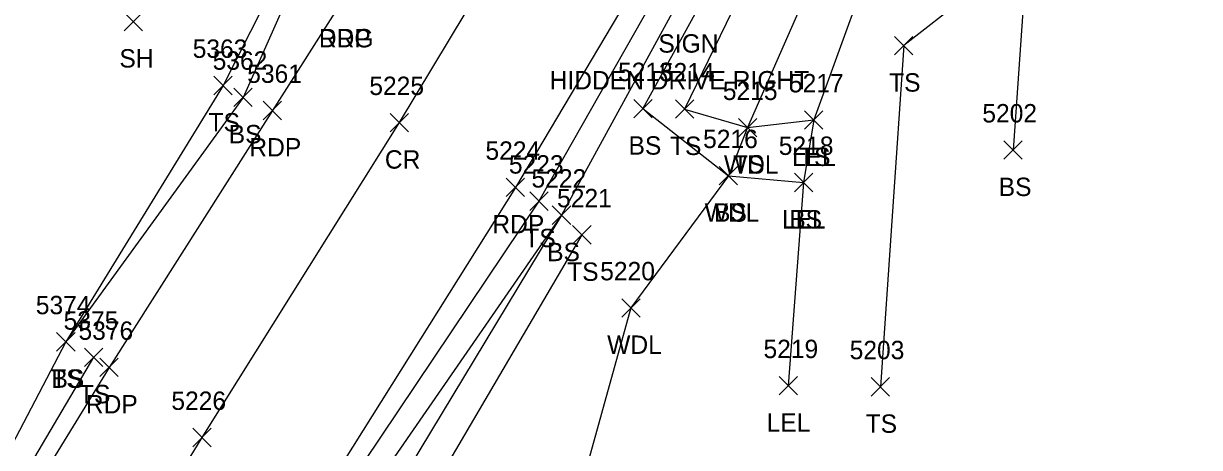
# Model space of a CAD drawing. Extents: x 1678863 to 1683592, y 407783 to 418211.
# Drawn here: x 1679773.8 to 1679901.7, y 411490.3 to 411536.4 of the extents above; entities that cross this region are included whole.
import ezdxf

# ---------------------------------------------------------------- set-up
doc = ezdxf.new("R2010")
doc.units = 0
for name, color, linetype in [('L_A', 7, 'Continuous'), ('L_I', 7, 'Continuous'), ('L_TIC', 7, 'Continuous'), ('LARO', 7, 'Continuous'), ('LAWA', 7, 'Continuous'), ('LELB', 7, 'Continuous'), ('P_A', 7, 'Continuous'), ('P_I', 7, 'Continuous'), ('P_TIC', 7, 'Continuous'), ('PET', 7, 'Continuous'), ('PRC', 7, 'Continuous'), ('R_A', 7, 'Continuous'), ('S_A', 7, 'Continuous'), ('S_C', 7, 'Continuous')]:
    doc.layers.add(name, color=color, linetype=linetype)

msp = doc.modelspace()

# ---------------------------------------------------------------- linework, layer by layer
at = {"layer": 'L_TIC'}
for points in [[(1679784.7, 411535.57), (1679786.7, 411537.57)], [(1679786.7, 411535.57), (1679784.7, 411537.57)], [(1679868.49, 411532.95), (1679870.49, 411534.95)], [(1679870.49, 411532.95), (1679868.49, 411534.95)], [(1679794.47, 411528.62), (1679796.47, 411530.62)], [(1679796.47, 411528.62), (1679794.47, 411530.62)], [(1679796.64, 411527.33), (1679798.64, 411529.33)], [(1679798.64, 411527.33), (1679796.64, 411529.33)], [(1679840.12, 411526.1), (1679842.12, 411528.1)], [(1679842.12, 411526.1), (1679840.12, 411528.1)], [(1679844.66, 411526.06), (1679846.66, 411528.06)], [(1679846.66, 411526.06), (1679844.66, 411528.06)], [(1679851.51, 411524.04), (1679853.51, 411526.04)], [(1679853.51, 411524.04), (1679851.51, 411526.04)], [(1679851.51, 411524.04), (1679853.51, 411526.04)], [(1679853.51, 411524.04), (1679851.51, 411526.04)], [(1679858.7, 411524.87), (1679860.7, 411526.87)], [(1679860.7, 411524.87), (1679858.7, 411526.87)], [(1679858.7, 411524.87), (1679860.7, 411526.87)], [(1679860.7, 411524.87), (1679858.7, 411526.87)], [(1679880.38, 411521.6), (1679882.38, 411523.6)], [(1679882.38, 411521.6), (1679880.38, 411523.6)], [(1679849.42, 411518.81), (1679851.42, 411520.81)], [(1679851.42, 411518.81), (1679849.42, 411520.81)], [(1679849.42, 411518.81), (1679851.42, 411520.81)], [(1679851.42, 411518.81), (1679849.42, 411520.81)], [(1679857.6, 411518.07), (1679859.6, 411520.07)], [(1679859.6, 411518.07), (1679857.6, 411520.07)], [(1679857.6, 411518.07), (1679859.6, 411520.07)], [(1679859.6, 411518.07), (1679857.6, 411520.07)], [(1679828.81, 411516.04), (1679830.81, 411518.04)], [(1679830.81, 411516.04), (1679828.81, 411518.04)], [(1679831.27, 411514.52), (1679833.27, 411516.52)], [(1679833.27, 411514.52), (1679831.27, 411516.52)], [(1679831.27, 411514.52), (1679833.27, 411516.52)], [(1679833.27, 411514.52), (1679831.27, 411516.52)], [(1679833.48, 411512.38), (1679835.48, 411514.38)], [(1679835.48, 411512.38), (1679833.48, 411514.38)], [(1679838.82, 411504.44), (1679840.82, 411506.44)], [(1679840.82, 411504.44), (1679838.82, 411506.44)], [(1679777.36, 411500.75), (1679779.36, 411502.75)], [(1679779.36, 411500.75), (1679777.36, 411502.75)], [(1679777.36, 411500.75), (1679779.36, 411502.75)], [(1679779.36, 411500.75), (1679777.36, 411502.75)], [(1679780.38, 411499.07), (1679782.38, 411501.07)], [(1679782.38, 411499.07), (1679780.38, 411501.07)], [(1679855.94, 411495.98), (1679857.94, 411497.98)], [(1679857.94, 411495.98), (1679855.94, 411497.98)], [(1679865.95, 411495.86), (1679867.95, 411497.86)], [(1679867.95, 411495.86), (1679865.95, 411497.86)]]:
    msp.add_lwpolyline(points, dxfattribs=at)
at = {"layer": 'LARO'}
msp.add_lwpolyline([(1679907.5, 411580.96), (1679887.83, 411574.32), (1679883.4, 411567.89), (1679867.65, 411547.72), (1679859.7, 411525.87), (1679858.6, 411519.07), (1679856.94, 411496.98)], dxfattribs=at)
at = {"layer": 'LAWA'}
msp.add_lwpolyline([(1680004.25, 411785.46), (1679976.9, 411753.1), (1679958.04, 411720.98), (1679943.68, 411696.76), (1679930.59, 411672.98), (1679924.11, 411664.99), (1679923.08, 411653), (1679912.44, 411634.31), (1679888.21, 411600.65), (1679877.2, 411570.14), (1679863.43, 411549.89), (1679852.51, 411525.04), (1679850.42, 411519.81), (1679839.82, 411505.44), (1679830.06, 411470.34), (1679799.34, 411443.02), (1679785.89, 411428.01), (1679782.74, 411411.85), (1679769.41, 411389.89), (1679761.73, 411378.81), (1679757.56, 411369.7), (1679753.34, 411358.46)], dxfattribs=at)
at = {"layer": 'LELB'}
for points in [[(1679916.52, 411674.28), (1679909.81, 411664.07), (1679898.36, 411642.32), (1679878.89, 411605.22), (1679863.63, 411575.73), (1679852.29, 411556.62), (1679829.81, 411517.04), (1679806.88, 411482.92), (1679785.94, 411449), (1679780.56, 411439.67)], [(1679912.89, 411662.57), (1679900.37, 411640.66), (1679881.44, 411603.9), (1679864.99, 411574.83), (1679854.21, 411555.65), (1679832.27, 411515.52), (1679808.94, 411481.73), (1679786.66, 411448.53), (1679780.56, 411439.67)], [(1679881.44, 411603.9), (1679867.49, 411573.38), (1679855.96, 411554.05), (1679841.12, 411527.1), (1679850.42, 411519.81), (1679858.6, 411519.07)], [(1679888.21, 411600.65), (1679870.41, 411571.95), (1679857.94, 411552.34), (1679845.66, 411527.06), (1679852.51, 411525.04), (1679859.7, 411525.87)], [(1679779.69, 411569.07), (1679801.41, 411552.27), (1679804.41, 411547.27), (1679795.47, 411529.62), (1679778.36, 411501.75)], [(1679904.65, 411568.89), (1679888.49, 411565.44), (1679888.37, 411545.52), (1679882.92, 411544.45), (1679869.49, 411533.95), (1679866.95, 411496.86)], [(1679883.4, 411567.89), (1679882.92, 411544.45), (1679881.38, 411522.6)], [(1679806.14, 411547.45), (1679797.64, 411528.33), (1679778.36, 411501.75), (1679763.64, 411473.68), (1679746.03, 411447.88), (1679723.06, 411418.16), (1679702.43, 411379.46), (1679690.59, 411343), (1679675.58, 411304.58), (1679662.66, 411263.35), (1679652.18, 411219.73), (1679640.47, 411176.73), (1679632.71, 411132.01), (1679618.53, 411081.8), (1679605.35, 411027.53), (1679595.31, 410983.65), (1679573.88, 410936.55), (1679563.6, 410891.23), (1679557.66, 410846.46), (1679539.41, 410796.62)], [(1679832.27, 411515.52), (1679810.95, 411480.21), (1679788.16, 411447.71), (1679780.56, 411439.67)], [(1679834.48, 411513.38), (1679813.74, 411478.06), (1679791.3, 411445.49), (1679780.7, 411437.27), (1679776.28, 411428.92), (1679774.72, 411423.33), (1679767.02, 411405.22), (1679761.89, 411400.09)], [(1679781.38, 411500.07), (1679765.06, 411472.52), (1679749.19, 411446.05), (1679730.91, 411413.61), (1679712.37, 411374.66), (1679697.7, 411340.33), (1679684.08, 411302.22), (1679670.53, 411260.95), (1679657.81, 411218.47), (1679646.65, 411174.55), (1679635.8, 411131.47), (1679623.71, 411080.94), (1679609.9, 411026.44), (1679598.95, 410982.42), (1679585.46, 410934.58), (1679575.03, 410887.7), (1679564.73, 410844.56), (1679552.33, 410794.24)]]:
    msp.add_lwpolyline(points, dxfattribs=at)
at = {"layer": 'P_TIC'}
for points in [[(1679799.83, 411525.9), (1679801.83, 411527.9)], [(1679801.83, 411525.9), (1679799.83, 411527.9)], [(1679813.63, 411524.58), (1679815.63, 411526.58)], [(1679815.63, 411524.58), (1679813.63, 411526.58)], [(1679826.26, 411517.54), (1679828.26, 411519.54)], [(1679828.26, 411517.54), (1679826.26, 411519.54)], [(1679782.06, 411497.97), (1679784.06, 411499.97)], [(1679784.06, 411497.97), (1679782.06, 411499.97)], [(1679792.16, 411490.35), (1679794.16, 411492.35)], [(1679794.16, 411490.35), (1679792.16, 411492.35)]]:
    msp.add_lwpolyline(points, dxfattribs=at)
at = {"layer": 'PET'}
for points in [[(1679867.25, 411644.06), (1679850.71, 411612.74), (1679839.15, 411591.9), (1679820.07, 411559.97), (1679808.39, 411538.76), (1679800.83, 411526.9), (1679783.06, 411498.97), (1679766.3, 411471.68), (1679750.8, 411444.97), (1679732.75, 411412.85), (1679713.65, 411374.02), (1679698.78, 411339.85), (1679685.17, 411301.91), (1679672.1, 411260.54), (1679659.99, 411217.72), (1679648.7, 411173.96), (1679637.67, 411131.16), (1679624.97, 411080.77), (1679611.27, 411026.39), (1679600.16, 410982.24), (1679587.76, 410934.2), (1679576.2, 410887.35), (1679565.67, 410844.22), (1679553.74, 410793.74)], [(1679896.74, 411643.04), (1679877.65, 411606.05), (1679861.74, 411576.87), (1679850.59, 411557.76), (1679827.26, 411518.54), (1679805.43, 411483.79), (1679784.24, 411450.11), (1679753.75, 411395.63), (1679739.59, 411364.36), (1679726.3, 411333.81), (1679713.56, 411299.83), (1679702.73, 411266.53), (1679688.63, 411217.52), (1679676.21, 411170.06), (1679662.5, 411116.26), (1679650.52, 411067.53), (1679638.18, 411018.28), (1679627.73, 410974.87), (1679616.7, 410931.33), (1679604.86, 410884.12), (1679594.89, 410843.79), (1679584.86, 410799.85)]]:
    msp.add_lwpolyline(points, dxfattribs=at)
at = {"layer": 'PRC'}
msp.add_lwpolyline([(1679884.42, 411649.11), (1679864.9, 411612.28), (1679849.33, 411584.21), (1679838.18, 411564.73), (1679814.63, 411525.58), (1679793.16, 411491.35), (1679772.02, 411456.74), (1679754.8, 411427.35), (1679741.76, 411402.46), (1679725.91, 411369.83), (1679712.56, 411339.15), (1679697.19, 411297.01), (1679684.62, 411257.06), (1679672.39, 411213.46), (1679661.84, 411172.03), (1679650.13, 411125.86), (1679638.58, 411078.33), (1679624.74, 411022.94), (1679613.91, 410978.69), (1679602.73, 410933.9), (1679590.95, 410887.12), (1679580.88, 410845.97), (1679570.75, 410804.03)], dxfattribs=at)

# ---------------------------------------------------------------- texts
at = {"layer": 'L_A'}
for s, p in [('SH', (1679784.19, 411531.57)), ('TS', (1679867.9, 411528.95)), ('TS', (1679793.88, 411524.62)), ('BS', (1679796.08, 411523.33)), ('BS', (1679839.56, 411522.1)), ('TS', (1679844.07, 411522.06)), ('LEL', (1679857.34, 411520.87)), ('TS', (1679858.11, 411520.87)), ('WDL', (1679849.93, 411520.04)), ('TS', (1679850.92, 411520.04)), ('BS', (1679879.82, 411517.6)), ('WDL', (1679847.84, 411514.81)), ('BS', (1679848.86, 411514.81)), ('LEL', (1679856.24, 411514.07)), ('BS', (1679857.04, 411514.07)), ('TS', (1679828.22, 411512.04)), ('BS', (1679830.71, 411510.52)), ('BS', (1679830.71, 411510.52)), ('TS', (1679832.89, 411508.38)), ('WDL', (1679837.24, 411500.44)), ('TS', (1679776.77, 411496.75)), ('BS', (1679776.8, 411496.75)), ('TS', (1679779.79, 411495.07)), ('LEL', (1679854.58, 411491.98)), ('TS', (1679865.35, 411491.86))]:
    msp.add_text(s, height=2, dxfattribs=at).set_placement(p)
at = {"layer": 'L_I'}
for s, p in [('5363', (1679792.16, 411532.62)), ('5362', (1679794.33, 411531.33)), ('5213', (1679838.42, 411530.1)), ('5214', (1679842.97, 411530.06)), ('5215', (1679849.82, 411528.04)), ('5215', (1679849.82, 411528.04)), ('5217', (1679857.01, 411528.87)), ('5217', (1679857.01, 411528.87)), ('5202', (1679878.04, 411525.6)), ('5216', (1679847.67, 411522.81)), ('5216', (1679847.67, 411522.81)), ('5218', (1679855.9, 411522.07)), ('5218', (1679855.9, 411522.07)), ('5223', (1679826.55, 411520.04)), ('5222', (1679829.01, 411518.52)), ('5222', (1679829.01, 411518.52)), ('5221', (1679831.79, 411516.38)), ('5220', (1679836.48, 411508.44)), ('5374', (1679775.1, 411504.75)), ('5374', (1679775.1, 411504.75)), ('5375', (1679778.12, 411503.07)), ('5219', (1679854.24, 411499.98)), ('5203', (1679863.61, 411499.86))]:
    msp.add_text(s, height=2, dxfattribs=at).set_placement(p)
at = {"layer": 'P_A'}
for s, p in [('RDP', (1679805.88, 411533.76)), ('RDP', (1679798.32, 411521.9)), ('CR', (1679813.06, 411520.58)), ('RDP', (1679824.75, 411513.54)), ('RDP', (1679780.54, 411493.97))]:
    msp.add_text(s, height=2, dxfattribs=at).set_placement(p)
at = {"layer": 'P_I'}
for s, p in [('5361', (1679798.09, 411529.9)), ('5225', (1679811.37, 411528.58)), ('5224', (1679824, 411521.54)), ('5376', (1679779.74, 411501.97)), ('5226', (1679789.84, 411494.35))]:
    msp.add_text(s, height=2, dxfattribs=at).set_placement(p)
at = {"layer": 'R_A'}
msp.add_text('DRG', height=2, dxfattribs=at).set_placement((1679805.88, 411533.76))
at = {"layer": 'S_A'}
msp.add_text('SIGN', height=2, dxfattribs=at).set_placement((1679842.81, 411533.19))
at = {"layer": 'S_C'}
msp.add_text('HIDDEN DRIVE RIGHT', height=2, dxfattribs=at).set_placement((1679830.98, 411529.19))

doc.saveas('drawing.dxf')
